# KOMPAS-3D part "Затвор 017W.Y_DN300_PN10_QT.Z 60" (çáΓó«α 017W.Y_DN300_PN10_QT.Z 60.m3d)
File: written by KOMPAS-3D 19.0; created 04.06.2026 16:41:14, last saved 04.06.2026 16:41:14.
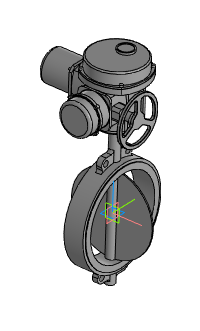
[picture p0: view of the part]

Document properties: Автор: Энергия; Полное имя файла: ..\..\..\3d для проектировщиков\017W разные\x.x Тип 017W.Y(S) Затвор дисковый поворотный межфланцевый\Затвор 017W.Y(S)_DN32-DN450_QT.Z\Затвор 017W.Y_DN300_PN10_QT.Z 60.a3d

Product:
- Part/product: Затвор 017W.Y_DN300_PN10_QT.Z 60
    Масса: 99.8472

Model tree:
1. Операция без истории:1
